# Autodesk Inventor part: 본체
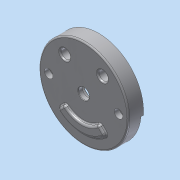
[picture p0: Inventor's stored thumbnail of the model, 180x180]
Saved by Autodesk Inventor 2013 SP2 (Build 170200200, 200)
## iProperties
Created: 2015-04
Part Number: 본체
Material: 알루미늄 6061
Document SubType Name: Modeling
Designer: dgall
Density: 2.71 g/cm^3
Mass: 1043.05 g
Surface Area: 1027.84 cm^2
Volume: 384.89 cm^3
Author: dgall
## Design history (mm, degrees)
sketch "스케치1"
  geometry: L1 (0, 0)-(-94.638, -8.28); L2 (95, 0)-(-95, 0); L3 (0, 0)-(94.638, -8.28); A1 r 95 centre (0, 0) between (-94.638, -8.28) and (-95, 0); 1 further point
  constraints: 6 end point, 4 point on circle, 1 centre point, 1 coincident, 1 horizontal, 1 midpoint
  dimensions: "d1" = 190 diameter of A1; "d5" = 5 deg angle of L2 L1; "d7" = 5 deg angle of L2 L3
extrude "돌출1" new body sketch "스케치1" distance "d3" = 32; taper "d4" = 0 deg
extrude "돌출2" cut sketch "스케치1" distance "d9" = 5; taper "d10" = 0 deg
sketch "스케치2"
  geometry: C1 r 90 at (0, 0); C2 r 15 at (40, -52); C3 r 10 at (40, -52); C4 r 10 at (-40, -52); C5 r 15 at (-40, -52); C6 r 5.5 at (74, 0); C7 r 5.5 at (-74, 0); A1 r 95 centre (0, 0) between (-94.638, 8.28) and (94.638, 8.28) reference; A2 r 95 centre (0, 0) between (94.638, 8.28) and (-94.638, 8.28) reference; 1 further point
  constraints: 7 centre point, 3 equal radius, 3 horizontal alignment, 2 coincident
  dimensions: "d16" = 180 diameter of C1; "d18" = 30 diameter of C2; "d19" = 20 diameter of C3; "d20" = 52 vertical distance of C4.centre point (0, 0); "d21" = 40 horizontal distance of point (0, 0) C2.centre; "d22" = 40 horizontal distance of C4.centre point (0, 0); "d25" = 11 diameter of C6; "d26" = 74 distance of point (0, 0) C6.centre; "d27" = 74 distance of A1.centre C7.centre
extrude "돌출3" cut sketch "스케치2" distance "d28" = 18; taper "d29" = 0 deg
sketch "스케치3"
  geometry: C1 r 90 at (0, 0) reference; C2 r 35 at (0, 0)
  constraints: 1 centre point, 1 coincident
  dimensions: "d30" = 70 diameter of C2
extrude "돌출4" join sketch "스케치3" distance "d33" = 10; taper "d34" = -10 deg
sketch "스케치4"
  geometry: C1 r 33.237 at (0, 0) reference; C2 r 25 at (0, 0); C3 r 11.5 at (0, 0)
  constraints: 2 centre point, 2 coincident
  dimensions: "d35" = 50 diameter of C2; "d37" = 23 diameter of C3
extrude "돌출5" cut sketch "스케치4" distance "d38" = 15; taper "d39" = 0 deg
extrude "돌출6" cut sketch "스케치4" stored distance "d40" = 15; taper "d41" = 0 deg
sketch "스케치5"
  geometry: L1 (76.916, -12)-(47.117, -12); L2 (-47.117, -12)-(-76.916, -12); C1 r 15 at (40, -52) reference; C2 r 15 at (-40, -52) reference; A1 r 10 centre (47.117, -22) between (47.117, -12) and (38.056, -17.769); A2 r 42 centre (0, 0) between (-38.056, -17.769) and (38.056, -17.769); A3 r 10 centre (-47.117, -22) between (-38.056, -17.769) and (-47.117, -12); A4 r 10 centre (-76.916, -22) between (-76.916, -12) and (-86.53, -24.75); A5 r 10 centre (76.916, -22) between (86.53, -24.75) and (76.916, -12); A6 r 90 centre (0, 0) between (-89.658, 7.844) and (89.658, 7.844) reference; A7 r 90 centre (0, 0) between (-86.53, -24.75) and (86.53, -24.75); 1 further point
  constraints: 12 point on circle, 7 tangent, 6 centre point, 4 end point, 4 equal radius, 2 collinear, 2 concentric, 1 horizontal
  dimensions: "d48" = 84 diameter of A2; "d49" = 10 radius of A5; "d50" = 12 distance from line of point (0, 0) L1; "d51" = 12 distance from line of L2 point (0, 0)
extrude "돌출7" cut sketch "스케치5" distance "d52" = 25; taper "d53" = 0 deg
sketch "스케치6"
  geometry: A1 r 90 centre (0, 0) between (86.53, -24.75) and (-86.53, -24.75) reference; A2 r 59 centre (0, 19) between (58.704, 13.1) and (-58.704, 13.1); A3 r 41 centre (0, 19) between (40.794, 14.9) and (-40.794, 14.9); A4 r 9 centre (49.749, 14) between (40.794, 14.9) and (58.704, 13.1); A5 r 9 centre (-49.749, 14) between (-58.704, 13.1) and (-40.794, 14.9)
  constraints: 8 point on circle, 4 centre point, 1 equal radius, 1 horizontal alignment, 1 vertical alignment
  dimensions: "d59" = 19 distance of A2.centre A1.centre; "d60" = 59 radius of A2; "d61" = 41 radius of A3; "d62" = 5 vertical distance of A4.centre A2.centre; "d63" = 9 radius of A4
extrude "돌출8" cut sketch "스케치6" distance "d64" = 7; taper "d65" = 0 deg
fillet "모깎기1" dims "d66" = 1
sketch "스케치7"
  geometry: C1 r 5.5 at (0, 0) reference; C2 r 9 at (0, 0); C3 r 5.5 at (-148, 0) reference; C4 r 9 at (-148, 0); 1 further point
  constraints: 2 centre point, 2 coincident
  dimensions: "d69" = 18 diameter of C2; "d70" = 18 diameter of C4
extrude "돌출9" join sketch "스케치7" stored distance "d71" = 7; taper "d72" = 0 deg
extrude "돌출10" cut sketch "스케치7" stored distance "d73" = 7; taper "d74" = 0 deg
sketch "스케치8"
  geometry: C1 r 5.5 at (74, 0) reference; C2 r 5.5 at (-74, 0) reference; C3 r 9 at (-74, 0); C4 r 9 at (74, 0)
  constraints: 2 centre point, 2 coincident
  dimensions: "d75" = 18 diameter of C3; "d77" = 18 diameter of C4
extrude "돌출11" cut sketch "스케치8" distance "d78" = 11; taper "d79" = 0 deg
extrude "돌출12" cut sketch "스케치2" stored distance "d80" = 11; taper "d81" = 0 deg
sketch "스케치9"
  geometry: L1 (0, -15)-(6, -15); L2 (6, -15)-(6, 15); L3 (6, 15)-(0, 15); L4 (0, -15)-(0, 15); L5 (-95, 0)-(-95, -6); L6 (-95, -6)-(-65, -6); L7 (-65, -6)-(-65, 0); L8 (-95, 0)-(-94.478, 0); L9 (-65, 0)-(-95, 0); C1 r 10 at (-80, 0) reference; A1 r 15 centre (0, 0) between (0, -15) and (0, 15) reference; A2 r 15 centre (-80, 0) between (-95, 0) and (-65, 0) reference; 1 further point
  constraints: 18 end point, 4 perpendicular, 4 point on circle, 4 tangent, 1 collinear, 1 horizontal, 1 parallel
  dimensions: "d82" = 6 distance between parallel lines of L2 L4; "d86" = 6 distance between parallel lines of L9 L6
extrude "돌출13" cut sketch "스케치9" distance "d84" = 3; taper "d85" = 0 deg
extrude "돌출14" cut sketch "스케치9" distance "d87" = 3; taper "d88" = 0 deg
chamfer "모따기1" distance "d89" = 1; stored, may be unused: second distance "d90" = 2, angle "d91" = 45 deg
chamfer "모따기2" distance "d92" = 1; stored, may be unused: second distance "d93" = 2, angle "d94" = 45 deg
fillet "모깎기2" dims "d95" = 3
fillet "모깎기3" dims "d96" = 3
fillet "모깎기4" dims "d97" = 3
chamfer "모따기3" distance "d98" = 1; stored, may be unused: second distance "d99" = 2, angle "d100" = 45 deg
sketch "스케치10"
  geometry: L1 (-50.912, -50.912)-(0, 0); L2 (50.912, -50.912)-(0, 0); L3 (0, 0)-(-74, 0); C1 r 92 at (0, 0) reference; C2 r 9 at (-74, 0) reference; A1 r 72 centre (0, 0) between (-50.912, -50.912) and (50.912, -50.912); A2 r 51 centre (0, 0) between (-36.062, -36.062) and (36.062, -36.062)
  constraints: 6 end point, 4 point on circle, 2 centre point, 2 coincident, 2 point on line, 1 horizontal
  dimensions: "d105" = 72 radius of A1; "d107" = 51 radius of A2; "d110" = 45 deg angle of L3 L1; "d111" = 45 deg angle of L3 L2
extrude "돌출15" join sketch "스케치10" distance "d112" = 5; taper "d113" = 0 deg
fillet "모깎기5" dims "d114" = 5
fillet "모깎기6" dims "d115" = 3
fillet "모깎기7" dims "d116" = 5
fillet "모깎기8" dims "d117" = 3
fillet "모깎기9" dims "d118" = 3
fillet "모깎기10" dims "d119" = 3
fillet "모깎기11" dims "d120" = 0.3
node "솔리드1"
mirror "대칭1"
mirror "대칭2"
